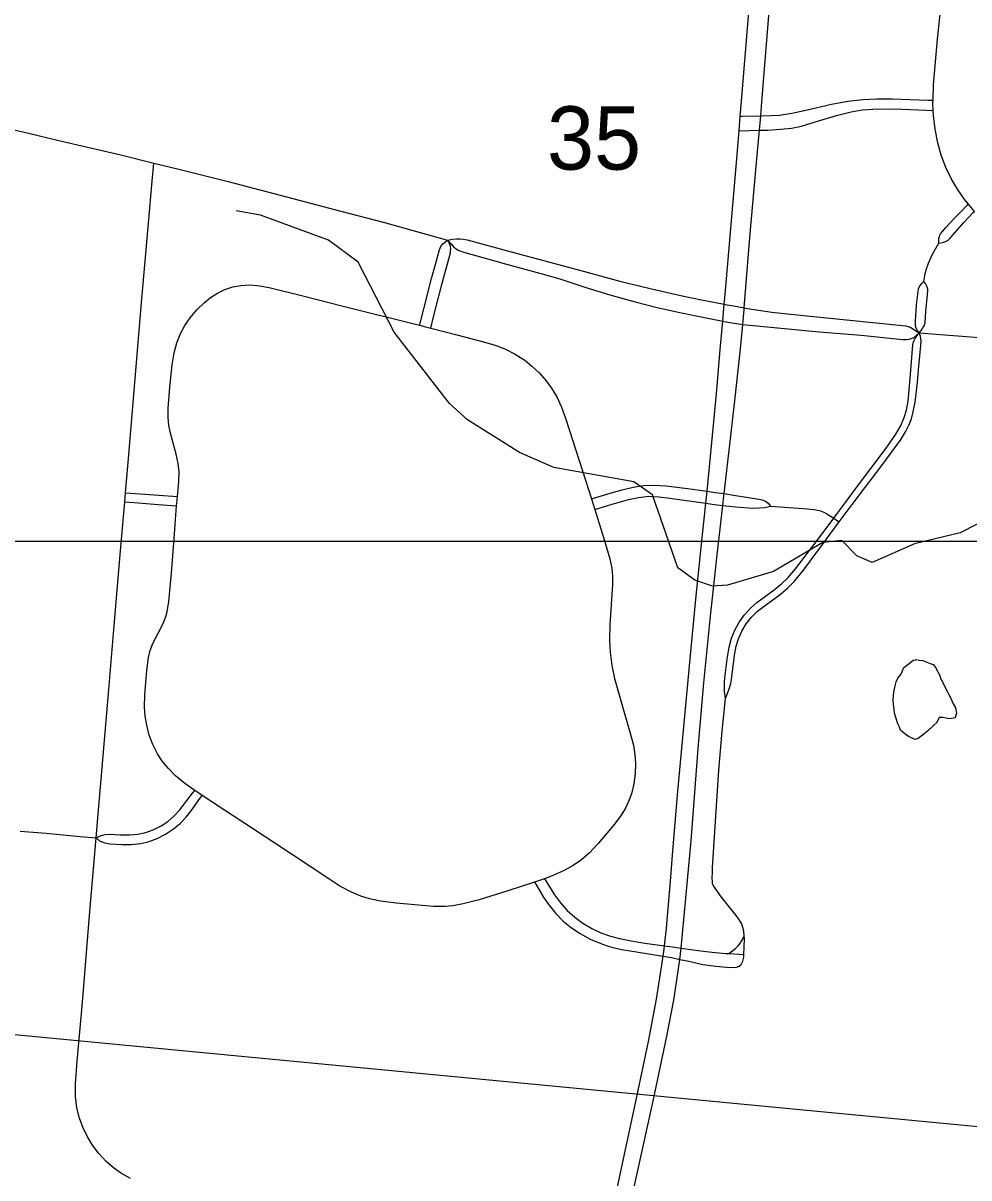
# Model space of a CAD drawing. Extents: x -1.4 to 35.4, y 0 to 22.
# Drawn here: x 26.463 to 27.089, y 13.645 to 14.409 of the extents above; entities that cross this region are included whole.
import ezdxf

# ---------------------------------------------------------------- set-up
doc = ezdxf.new("R2010")
doc.units = 0
for name, color, linetype in [('GM_X_City_Street', 7, 'Continuous'), ('GM_X_County_Road', 7, 'Continuous'), ('GM_X_County_Text', 7, 'Continuous'), ('GM_X_Minor_Lake', 7, 'Continuous'), ('GM_X_Minor_River', 7, 'Continuous'), ('GM_X_Section', 7, 'Continuous'), ('GM_X_Section_Text', 7, 'Continuous')]:
    doc.layers.add(name, color=color, linetype=linetype)

msp = doc.modelspace()

# ---------------------------------------------------------------- linework, layer by layer
at = {"layer": 'GM_X_City_Street'}
for p, q in [((26.91553, 14.09944), (26.92089, 14.0987)), ((26.91471, 14.09156), (26.92037, 14.09076)), ((26.92779, 13.96242), (26.92818, 13.96341)), ((26.88733, 13.79876), (26.89261, 13.79803)), ((26.8864, 13.79186), (26.89204, 13.79093))]:
    msp.add_line(p, q, dxfattribs=at)
for points in [[(27.09241, 14.28454), (27.08842, 14.28935), (27.08616, 14.2921), (27.08127, 14.29911), (27.07726, 14.30594), (27.07356, 14.31364), (27.07055, 14.32163), (27.06819, 14.32985), (27.06639, 14.33884), (27.0653, 14.34793), (27.06519, 14.35133), (27.06502, 14.35648), (27.06506, 14.35804), (27.06538, 14.36817), (27.068, 14.39846), (27.07145, 14.43179)], [(26.93671, 14.33772), (26.95018, 14.33817), (26.95568, 14.33835), (26.96419, 14.33885), (26.97135, 14.3396), (26.97795, 14.34097), (26.98858, 14.34422), (27.00108, 14.34804), (27.01081, 14.3504), (27.01825, 14.35159), (27.02512, 14.35213), (27.03934, 14.35225), (27.06072, 14.35149), (27.06519, 14.35133)], [(26.93753, 14.3474), (26.93869, 14.34744), (26.95101, 14.34779), (26.95784, 14.34798), (26.96344, 14.34825), (26.9717, 14.34952), (26.98087, 14.35144), (26.99778, 14.35545), (27.00874, 14.35736), (27.01854, 14.3586), (27.02778, 14.35906), (27.03827, 14.3589), (27.06167, 14.35815), (27.06506, 14.35804)], [(26.53414, 13.64481), (26.52801, 13.64827), (26.52277, 13.65196), (26.51793, 13.65614), (26.51312, 13.6613), (26.50891, 13.66693), (26.50529, 13.67295), (26.50253, 13.67872), (26.50032, 13.68472), (26.49862, 13.69155), (26.49766, 13.69917), (26.49759, 13.70743), (26.49868, 13.72242), (26.50206, 13.75893), (26.50711, 13.8215), (26.51131, 13.87014), (26.51267, 13.8859), (26.51724, 13.9398), (26.5198, 13.96826), (26.52297, 14.00791), (26.52751, 14.0599), (26.53023, 14.09241), (26.53074, 14.09843), (26.53306, 14.12617), (26.54106, 14.22153), (26.54609, 14.27911), (26.5482, 14.30205), (26.54953, 14.31645)], [(27.06895, 14.26357), (27.069, 14.26609), (27.06909, 14.26717), (27.06927, 14.26801), (27.06956, 14.26884), (27.06997, 14.26976), (27.07352, 14.2739), (27.07905, 14.27975), (27.08358, 14.28444), (27.08765, 14.28857), (27.08842, 14.28935)], [(27.06895, 14.26357), (27.07123, 14.26396), (27.07337, 14.26456), (27.07423, 14.26496), (27.07505, 14.26552), (27.07613, 14.26655), (27.08085, 14.27197), (27.08536, 14.27709), (27.09171, 14.2838), (27.09241, 14.28454)], [(26.72527, 14.20922), (26.72582, 14.21138), (26.72807, 14.22017), (26.73327, 14.24004), (26.73581, 14.24945), (26.73834, 14.25853), (26.73892, 14.26017), (26.73962, 14.26164), (26.74067, 14.26311), (26.74172, 14.26402), (26.74376, 14.26549)], [(26.73271, 14.20732), (26.73436, 14.21393), (26.74015, 14.23627), (26.74571, 14.25705), (26.74586, 14.25849), (26.74592, 14.25996), (26.74571, 14.2615), (26.74522, 14.26311), (26.74459, 14.26437), (26.74376, 14.26549)], [(27.05905, 14.23807), (27.05965, 14.2421), (27.06049, 14.24594), (27.06201, 14.25032), (27.06473, 14.2563), (27.06895, 14.26357)], [(26.92779, 13.96242), (26.92718, 13.96687), (26.92704, 13.97008), (26.92709, 13.97316), (26.92733, 13.97598), (26.92881, 13.98833), (26.93012, 13.99629), (26.93176, 14.00227), (26.93385, 14.00745), (26.93652, 14.01236), (26.94009, 14.01743), (26.94424, 14.02204), (26.9484, 14.02577), (26.95994, 14.03419), (26.96475, 14.03809), (26.96919, 14.04242), (26.97404, 14.04806), (26.9891, 14.0678), (26.99934, 14.08151), (27.01584, 14.10361), (27.03405, 14.12798), (27.04049, 14.13711), (27.04353, 14.14251), (27.04603, 14.14819), (27.04747, 14.15294), (27.04853, 14.15905), (27.04989, 14.17389), (27.05179, 14.19615), (27.05201, 14.19766), (27.05253, 14.19919), (27.05315, 14.20044), (27.054, 14.20163), (27.05587, 14.2043), (27.05485, 14.20571), (27.054, 14.20731), (27.05355, 14.20878), (27.05343, 14.21059), (27.05349, 14.21184), (27.05417, 14.22263), (27.05491, 14.22977), (27.05545, 14.23321), (27.05635, 14.23518), (27.05773, 14.2369), (27.05905, 14.23807)], [(26.92818, 13.96341), (26.92932, 13.96639), (26.93033, 13.96938), (26.93122, 13.97222), (26.93175, 13.97486), (26.93365, 13.99091), (26.93485, 13.997), (26.93634, 14.00174), (26.93864, 14.00683), (26.9415, 14.01164), (26.94491, 14.01607), (26.94886, 14.02002), (26.95326, 14.02347), (26.96387, 14.03107), (26.96906, 14.0355), (26.9734, 14.03995), (26.97927, 14.04718), (26.99191, 14.06411), (27.00297, 14.07912), (27.01145, 14.09062), (27.03178, 14.11734), (27.04401, 14.13379), (27.04684, 14.13861), (27.04901, 14.14317), (27.05075, 14.14726), (27.05202, 14.15192), (27.0532, 14.15839), (27.05473, 14.17156), (27.05576, 14.18218), (27.05708, 14.19575), (27.05718, 14.19868), (27.05701, 14.20027), (27.05667, 14.20174), (27.05587, 14.2043), (27.0574, 14.20606), (27.05842, 14.20742), (27.05928, 14.20878), (27.05956, 14.20974), (27.05978, 14.21122), (27.06034, 14.21818), (27.06149, 14.22962), (27.06166, 14.23195), (27.06156, 14.23312), (27.06105, 14.23499), (27.06015, 14.23684), (27.05905, 14.23807)], [(26.56507, 14.09587), (26.56613, 14.10584), (26.5662, 14.11216), (26.56567, 14.11782), (26.56437, 14.12398), (26.56058, 14.13775), (26.55951, 14.14314), (26.55904, 14.14799), (26.55905, 14.15413), (26.55997, 14.16834), (26.56152, 14.18312), (26.56291, 14.19099), (26.56473, 14.19748), (26.56722, 14.20372), (26.57009, 14.20912), (26.57351, 14.21418), (26.57786, 14.21934), (26.58268, 14.22405), (26.58697, 14.22748), (26.59159, 14.23041), (26.59655, 14.23276), (26.60174, 14.23452), (26.60707, 14.23557), (26.61252, 14.23585), (26.618, 14.23546), (26.62588, 14.23407), (26.64817, 14.22864), (26.67468, 14.22192), (26.72527, 14.20922)], [(26.72527, 14.20922), (26.72925, 14.20822), (26.73271, 14.20732)], [(26.73271, 14.20732), (26.75081, 14.20267), (26.76764, 14.19832), (26.77591, 14.19582), (26.78219, 14.19338), (26.78822, 14.19037), (26.79489, 14.18601), (26.7997, 14.1822), (26.80461, 14.17757), (26.80909, 14.17253), (26.8127, 14.16759), (26.81613, 14.16179), (26.81921, 14.1551), (26.82217, 14.14699), (26.83511, 14.10679), (26.83912, 14.09438)], [(26.83912, 14.09438), (26.8515, 14.09809), (26.85926, 14.10042), (26.86661, 14.10222), (26.87348, 14.10317), (26.88041, 14.10341), (26.88857, 14.10295), (26.90253, 14.10124), (26.91553, 14.09944)], [(26.53023, 14.09241), (26.53649, 14.09192), (26.55236, 14.09066), (26.56447, 14.08971)], [(26.53074, 14.09843), (26.54039, 14.09771), (26.55591, 14.09655), (26.56507, 14.09587)], [(26.56447, 14.08971), (26.56462, 14.09163), (26.56507, 14.09587)], [(26.83912, 14.09438), (26.84027, 14.09083), (26.84132, 14.08743)], [(26.84132, 14.08743), (26.85273, 14.09079), (26.86349, 14.09397), (26.8702, 14.09537), (26.877, 14.09611), (26.88363, 14.09573), (26.89099, 14.09488), (26.91471, 14.09156)], [(26.92089, 14.0987), (26.9268, 14.09784), (26.93301, 14.09693), (26.94292, 14.09539), (26.94977, 14.09427), (26.95191, 14.09375), (26.95415, 14.09283), (26.95589, 14.09161), (26.95756, 14.08951)], [(26.57651, 13.90157), (26.57005, 13.90609), (26.56389, 13.91117), (26.55913, 13.91594), (26.55528, 13.92069), (26.55195, 13.92581), (26.54889, 13.93181), (26.54649, 13.9381), (26.54476, 13.9446), (26.54379, 13.95064), (26.5434, 13.95675), (26.54361, 13.96476), (26.54495, 13.98083), (26.54601, 13.98937), (26.54714, 13.99409), (26.54883, 13.99862), (26.55219, 14.00521), (26.5556, 14.01193), (26.55738, 14.01666), (26.55821, 14.01971), (26.55936, 14.02654), (26.56108, 14.04515), (26.56291, 14.06808), (26.56447, 14.08971)], [(26.84132, 14.08743), (26.84721, 14.06827), (26.85128, 14.05464), (26.85246, 14.04865), (26.85293, 14.04317), (26.85292, 14.03765), (26.85123, 14.01101), (26.85096, 14.00101), (26.85134, 13.99288), (26.85248, 13.98418), (26.85434, 13.97562), (26.85878, 13.96004), (26.86431, 13.94096), (26.8668, 13.93139), (26.86783, 13.92536), (26.86823, 13.91926), (26.86799, 13.91253), (26.86709, 13.90584), (26.86551, 13.89931), (26.86365, 13.89415), (26.86152, 13.88977), (26.85865, 13.88508), (26.85423, 13.87915), (26.84343, 13.86638), (26.83748, 13.86015), (26.83239, 13.85573), (26.82689, 13.85185), (26.82102, 13.84854), (26.81314, 13.84504), (26.80793, 13.84316)], [(26.92037, 14.09076), (26.92592, 14.09007), (26.93431, 14.08902), (26.94599, 14.08833), (26.95017, 14.08834), (26.95374, 14.08857), (26.95756, 14.08951)], [(26.95756, 14.08951), (26.97919, 14.08791), (26.98619, 14.08734), (26.99004, 14.08658), (26.99329, 14.08546), (26.99477, 14.08452), (26.99934, 14.08151), (27.00184, 14.07986), (27.00297, 14.07912)], [(26.9399, 13.79304), (26.94011, 13.79783), (26.94031, 13.8035), (26.94014, 13.8053), (26.93983, 13.80852), (26.93847, 13.81333), (26.93573, 13.81766), (26.92515, 13.83094), (26.92087, 13.83693), (26.9199, 13.83843), (26.91923, 13.84002), (26.91903, 13.84134), (26.9189, 13.84359), (26.91904, 13.84731), (26.91916, 13.85055), (26.92335, 13.91488), (26.92551, 13.94083), (26.92779, 13.96242)], [(26.51131, 13.87014), (26.51351, 13.87124), (26.51557, 13.872), (26.51719, 13.87236), (26.52027, 13.87265), (26.5274, 13.87226), (26.5335, 13.87212), (26.53894, 13.87262), (26.54427, 13.87378), (26.5494, 13.8756), (26.55428, 13.87805), (26.55882, 13.88108), (26.56295, 13.88465), (26.56663, 13.88869), (26.57514, 13.89978), (26.57651, 13.90157)], [(26.58151, 13.89822), (26.57866, 13.90008), (26.57651, 13.90157)], [(26.51131, 13.87014), (26.51343, 13.86816), (26.51505, 13.86743), (26.51702, 13.86687), (26.52033, 13.86624), (26.52829, 13.86583), (26.53458, 13.8658), (26.54083, 13.86654), (26.54635, 13.86786), (26.55168, 13.86977), (26.55731, 13.87259), (26.56258, 13.87605), (26.56691, 13.87971), (26.57077, 13.88386), (26.57416, 13.88798), (26.58003, 13.89615), (26.58151, 13.89822)], [(26.80146, 13.84086), (26.78378, 13.83512), (26.7648, 13.82928), (26.75406, 13.82642), (26.74742, 13.82523), (26.74194, 13.82476), (26.73457, 13.82482), (26.70985, 13.82703), (26.69943, 13.82829), (26.69223, 13.8298), (26.68639, 13.83163), (26.68018, 13.83427), (26.67257, 13.8383), (26.6653, 13.84296), (26.62959, 13.86668), (26.59634, 13.88854), (26.58151, 13.89822)], [(26.461, 13.87467), (26.47834, 13.8733), (26.50065, 13.87116), (26.51131, 13.87014)], [(26.80793, 13.84316), (26.8021, 13.84106), (26.80146, 13.84086)], [(26.80146, 13.84086), (26.8022, 13.83962), (26.8072, 13.83126), (26.81078, 13.82596), (26.81556, 13.82009), (26.82043, 13.81514), (26.82577, 13.81069), (26.83155, 13.80682), (26.83822, 13.80324), (26.84521, 13.80033), (26.84935, 13.79874), (26.85398, 13.79746), (26.85916, 13.79638), (26.86876, 13.79477), (26.8864, 13.79186)], [(26.80793, 13.84316), (26.80883, 13.8417), (26.81163, 13.83716), (26.81451, 13.83249), (26.81848, 13.82708), (26.82301, 13.82214), (26.82803, 13.81767), (26.83344, 13.81369), (26.8392, 13.81024), (26.84528, 13.80738), (26.85159, 13.80515), (26.85769, 13.80356), (26.86522, 13.80214), (26.8743, 13.80058), (26.88733, 13.79876)], [(26.92997, 13.79363), (26.93089, 13.79434), (26.93442, 13.79706), (26.93611, 13.79867), (26.9377, 13.80063), (26.93908, 13.80287), (26.93976, 13.80443), (26.94014, 13.8053)], [(26.89261, 13.79803), (26.89843, 13.79723), (26.9112, 13.79547), (26.91886, 13.79462), (26.92766, 13.79377), (26.92997, 13.79363), (26.93678, 13.79321), (26.9399, 13.79304)], [(26.89204, 13.79093), (26.89759, 13.78976), (26.90354, 13.78852), (26.91276, 13.78639), (26.92128, 13.78525), (26.92851, 13.78469), (26.93231, 13.78451), (26.93495, 13.78464), (26.93685, 13.78525), (26.93818, 13.7864), (26.93929, 13.78858), (26.93983, 13.79135), (26.9399, 13.79304)]]:
    msp.add_lwpolyline(points, dxfattribs=at)
at = {"layer": 'GM_X_County_Road'}
msp.add_line((26.95018, 14.33817), (26.95101, 14.34779), dxfattribs=at)
for points in [[(26.95101, 14.34779), (26.9518, 14.357), (26.95723, 14.42508), (26.95875, 14.45232), (26.95958, 14.47201), (26.95948, 14.47691), (26.95904, 14.48098), (26.95864, 14.48295), (26.95822, 14.48465), (26.95598, 14.49029)], [(26.85626, 13.63941), (26.869, 13.69898), (26.87674, 13.73547), (26.8821, 13.76358), (26.88476, 13.78041), (26.8864, 13.79186), (26.88707, 13.79647), (26.88733, 13.79876), (26.88865, 13.81051), (26.89167, 13.84427), (26.89275, 13.85877), (26.89596, 13.89873), (26.90457, 13.99089), (26.90801, 14.028), (26.91187, 14.06443), (26.91471, 14.09156), (26.91553, 14.09944), (26.91698, 14.11325), (26.92173, 14.16399), (26.92446, 14.19557), (26.92592, 14.212), (26.9269, 14.22309), (26.92748, 14.22959), (26.93494, 14.31687), (26.93671, 14.33772), (26.93753, 14.3474), (26.93793, 14.35215), (26.94371, 14.4215)], [(26.2692, 14.38463), (26.27651, 14.38276), (26.3049, 14.37586), (26.33383, 14.36871), (26.35375, 14.36385), (26.37062, 14.35964), (26.4014, 14.35213), (26.42369, 14.34665), (26.44839, 14.34038), (26.46658, 14.33622), (26.48652, 14.33147), (26.50468, 14.3273), (26.52765, 14.3219), (26.54953, 14.31645)], [(26.93915, 14.2097), (26.94005, 14.21963), (26.94014, 14.22076), (26.9439, 14.26731), (26.94877, 14.32173), (26.95018, 14.33817)], [(26.54953, 14.31645), (26.56681, 14.31215), (26.59875, 14.30421), (26.64139, 14.29297), (26.67322, 14.2846), (26.70214, 14.27722), (26.74376, 14.26549)], [(26.74376, 14.26549), (26.74704, 14.26619), (26.7497, 14.26633), (26.75201, 14.26633), (26.75439, 14.26612), (26.75677, 14.2657), (26.78357, 14.25854), (26.83211, 14.2454), (26.85791, 14.23846), (26.8778, 14.23347), (26.89901, 14.22867), (26.91178, 14.226), (26.9269, 14.22309), (26.92893, 14.22278)], [(26.74376, 14.26549), (26.74543, 14.26381), (26.7462, 14.26304), (26.74704, 14.26206), (26.74809, 14.26087), (26.74921, 14.25996), (26.7504, 14.25912), (26.75195, 14.25835), (26.75537, 14.25723), (26.7672, 14.25401), (26.78275, 14.24971), (26.80557, 14.24353), (26.81811, 14.23983), (26.83469, 14.23448), (26.85128, 14.22931), (26.86801, 14.22459), (26.88244, 14.22094), (26.89758, 14.21757), (26.91281, 14.21454), (26.92592, 14.212)], [(26.92893, 14.22278), (26.93298, 14.22216), (26.94014, 14.22076), (26.94234, 14.22037), (26.95833, 14.21791), (26.97068, 14.21645), (27.04697, 14.20878), (27.04861, 14.20838), (27.04986, 14.20787), (27.05105, 14.20725), (27.05213, 14.20657), (27.05366, 14.2056), (27.05587, 14.2043)], [(26.92592, 14.212), (26.92937, 14.21133), (26.93915, 14.2097), (26.98971, 14.20495), (27.01743, 14.2026), (27.04475, 14.19987), (27.04748, 14.19987), (27.04935, 14.2001), (27.05054, 14.20038), (27.05196, 14.20089), (27.0532, 14.20174), (27.05587, 14.2043)], [(26.92989, 14.12454), (26.93389, 14.15915), (26.93769, 14.1937), (26.93915, 14.2097)], [(27.05587, 14.2043), (27.10125, 14.20074), (27.12478, 14.19842), (27.14829, 14.19622), (27.17241, 14.19398), (27.20456, 14.19104), (27.22865, 14.18876), (27.25216, 14.18655), (27.27568, 14.18443), (27.28916, 14.18319)], [(26.92592, 14.09007), (26.92661, 14.09622), (26.9268, 14.09784), (26.92989, 14.12454)], [(26.91875, 14.02495), (26.92204, 14.05548), (26.92592, 14.09007)], [(26.89759, 13.78976), (26.89843, 13.79723), (26.90495, 13.86829), (26.90962, 13.92934), (26.91342, 13.97268), (26.91812, 14.01904), (26.91875, 14.02495)], [(26.87932, 13.69314), (26.87953, 13.6941), (26.88873, 13.73787), (26.89352, 13.76289), (26.89759, 13.78976)], [(26.86172, 13.61083), (26.86252, 13.61536), (26.86273, 13.6164), (26.86653, 13.63525), (26.87932, 13.69314)]]:
    msp.add_lwpolyline(points, dxfattribs=at)
msp.add_lwpolyline([(26.32634, 13.05458), (27.33112, 13.05458), (27.3811, 13.65162), (26.39247, 13.74598)], close=True, dxfattribs=at)
at = {"layer": 'GM_X_County_Text'}
msp.add_lwpolyline([(24.48967, 15.27515), (24.48967, 14.06648), (28.48645, 14.06648)], dxfattribs=at)
at = {"layer": 'GM_X_Minor_Lake'}
msp.add_lwpolyline([(27.05494, 13.98762), (27.05608, 13.9876), (27.05836, 13.98757), (27.061, 13.98638), (27.06326, 13.98559), (27.06515, 13.9848), (27.06664, 13.98288), (27.06959, 13.97751), (27.07031, 13.97522), (27.07142, 13.9733), (27.07252, 13.971), (27.07436, 13.96718), (27.07546, 13.96488), (27.07657, 13.96296), (27.0784, 13.95875), (27.07988, 13.95607), (27.08058, 13.95264), (27.07978, 13.94962), (27.07597, 13.94892), (27.0737, 13.94934), (27.07181, 13.94975), (27.06915, 13.94979), (27.06758, 13.9464), (27.06527, 13.94454), (27.06142, 13.94081), (27.05911, 13.93894), (27.05719, 13.93745), (27.05526, 13.93597), (27.05297, 13.93525), (27.05072, 13.93642), (27.04883, 13.93721), (27.04658, 13.93877), (27.04358, 13.94148), (27.04286, 13.94339), (27.04175, 13.94569), (27.03958, 13.95256), (27.03925, 13.9556), (27.03891, 13.95827), (27.03859, 13.96169), (27.03901, 13.96434), (27.03905, 13.96662), (27.03946, 13.96851), (27.04026, 13.97153), (27.04067, 13.97343), (27.04185, 13.97569), (27.04379, 13.97831), (27.04458, 13.9802), (27.04576, 13.98284), (27.04922, 13.98544), (27.05191, 13.98767), (27.05381, 13.98802), (27.0542, 13.9884), (27.05381, 13.98802)], dxfattribs=at)
at = {"layer": 'GM_X_Minor_River'}
msp.add_lwpolyline([(27.12623, 14.09388), (27.08292, 14.07199), (27.05281, 14.06463), (27.02487, 14.0523), (27.01471, 14.05668), (27.00467, 14.06676), (26.99213, 14.0655), (26.9595, 14.04643), (26.92897, 14.03719), (26.9191, 14.03663), (26.90742, 14.04066), (26.8962, 14.04887), (26.87933, 14.09705), (26.86699, 14.10565), (26.81407, 14.11509), (26.79151, 14.12504), (26.75704, 14.14663), (26.74512, 14.15751), (26.7085, 14.20457), (26.68477, 14.25099), (26.66496, 14.26545), (26.62015, 14.28193), (26.60389, 14.28493)], dxfattribs=at)
at = {"layer": 'GM_X_Section'}
msp.add_lwpolyline([(27.48098, 14.67461), (27.3811, 13.65162), (26.39247, 13.74598), (26.47381, 14.7481)], close=True, dxfattribs=at)

# ---------------------------------------------------------------- texts
at = {"layer": 'GM_X_Section_Text'}
msp.add_text('35', height=0.041856, rotation=0.00001, dxfattribs=at).set_placement((26.80964, 14.31214))

doc.saveas('drawing.dxf')
